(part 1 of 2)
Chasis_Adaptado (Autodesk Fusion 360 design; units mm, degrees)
part number: 2026-02-16-18-52-57-349
description: 18650
part number: Porta baterias 2x18650
description: Porta baterias 2x18650
description: Contacto_Helice_v2.0
part number: Contacto_Helice_v2.0
description: Contacto_plano_v1.0
part number: Contacto_plano_v1.0
description: Bateria 18650
part number: Bateria 18650
description: remache_v1.0
part number: remache_v1.0
description: STEP AP214
part number: DRV8833
part number: esp32_Wroom_30pins_C-Type
description: Part Number
part number: N20 Mini Micro Metall Gear Motor DC 3-6-12V v1
external_derived "DerivadoExterno1"
derived_instance "DerivedInstance1"
derived_instance "DerivedInstance1"
derived_instance "DerivedInstance2"
derived_instance "DerivedInstance3"
derived_instance "DerivedInstance4"
derived_instance "DerivedInstance5"
external_derived "DerivadoExterno2"
derived_instance "DerivedInstance2"
external_derived "DerivadoExterno3"
derived_instance "DerivedInstance3"
external_derived "DerivadoExterno5"
derived_instance "DerivedInstance5"
sketch "Boceto1" plane through (0, 0, 0) normal (0, 0, 1) x axis (1, 0, 0)
position "Posición1"
sketch "Boceto2" plane through (0, 0, 0) normal (0, 0, 1) x axis (1, 0, 0)
sketch "Boceto3" plane through (0, 0, 0) normal (0, 0, 1) x axis (1, 0, 0)
  line L1 (66.5, -10) -> (0, -10)
  line L2 (66.5, -26.4) -> (66.5, -10)
  line L3 (0, -26.4) -> (66.5, -26.4)
  line L4 (0, -10) -> (0, -26.4)
  point P2 (0, -10)
  point P3 (66.5, -10)
  point P5 (0, -26.4)
  horizontal L1
  vertical L2
  horizontal L3
  vertical L4
  dimension "d3" distance P2 P3 = 66.5
  dimension "d4" distance P2 P5 = 16.4
extrude "Extruir1" new body sketch "Boceto3" along normal blind 3.5
move "Desplazar1"
move "Desplazar2" PositionX -33.25 PositionY 128.46 PositionZ 40.82
sketch "Boceto4" plane through (0, 0, 0) normal (0, 0, 1) x axis (1, 0, 0)
  circle C1 centre (20, -70) radius 19
  dimension "d10" diameter C1 = 38
copy_paste_bodies "CopiarPegarCuerpos1"
move "Desplazar4"
sketch "Boceto5" plane through (0, 0, 0) normal (0, 0, 1) x axis (1, 0, 0)
extrude "Extruir3" add of existing geometry blind 15
offset_faces "CarasDesfase3" distance -4
move "Desplazar5"
copy_paste_bodies "CopiarPegarCuerpos2"
move "Desplazar6"
move "Desplazar7"
move "Desplazar8" PositionX -60 PositionY 14.925 PositionZ 0
move "Desplazar9" PositionX -60 PositionY 15 PositionZ 0
move "Desplazar10" PositionX 60 PositionY 15 PositionZ 0
move_face "MoveFace1"
move "Desplazar11"
move "Desplazar12"
move "Desplazar1"
scale "Escala1" ScaleFactor 1.0557
copy_paste "CopiarPegar"
position "Posición2"
hole "Agujero1" HoleDepth 14 HoleDiameter 3 TipAngle 180
position "Posición3"
extrude "Extruir4" add of existing geometry blind 0.5
position "Posición4"
sketch "Boceto6" plane through (0, 0, 0) normal (1, 0, 0) x axis (0, 1, 0)
  line L1 (145.5, 9.7) -> (5.5, 9.7)
  line L2 (145.5, 5.7) -> (145.5, 9.7)
  line L3 (5.5, 5.7) -> (145.5, 5.7)
  line L4 (5.5, 9.7) -> (5.5, 5.7)
  point P2 (5.5, 9.7)
  point P3 (145.5, 9.7)
  point P5 (5.5, 5.7)
  horizontal L1
  vertical L2
  horizontal L3
  vertical L4
  dimension "d33" distance P2 P3 = 140
  dimension "d34" distance P2 P5 = 4
extrude "Extruir5" new body sketch "Boceto6" along normal blind 4
move "Desplazar13"
extrude "Extruir6" add of existing geometry blind 22
extrude "Extruir7" add of existing geometry blind 26
move "Desplazar14"
position "Posición5"
sketch "Boceto7" plane through (0, 0, 0) normal (0, 0, 1) x axis (1, 0, 0)
  line L1 (32, -10) -> (10, -10)
  line L2 (32, -32) -> (32, -10)
  line L3 (10, -32) -> (32, -32)
  line L4 (10, -10) -> (10, -32)
  point P2 (10, -10)
  point P3 (32, -10)
  point P5 (10, -32)
  horizontal L1
  vertical L2
  horizontal L3
  vertical L4
  dimension "d41" distance P2 P3 = 22
  dimension "d42" distance P2 P5 = 22
extrude "Extruir8" new body sketch "Boceto7" along normal blind 15
move "Desplazar15"
move "Desplazar16" PositionX -1 PositionY -32 PositionZ -11
move "Desplazar17" PositionX -11 PositionY 110 PositionZ 0
extrude "Extruir9" add of existing geometry blind 5
sketch "Boceto8" plane through (0, 0, 0) normal (0, 0, 1) x axis (1, 0, 0)
  line L1 (-4, -5) -> (-20, -5)
  line L2 (-4, -35) -> (-4, -5)
  line L3 (-20, -35) -> (-4, -35)
  line L4 (-20, -5) -> (-20, -35)
  point P2 (-20, -5)
  point P3 (-4, -5)
  point P5 (-20, -35)
  horizontal L1
  vertical L2
  horizontal L3
  vertical L4
  dimension "d53" distance P2 P3 = 16
  dimension "d54" distance P2 P5 = 30
extrude "Extruir10" new body sketch "Boceto8" along normal blind 50
offset_faces "CarasDesfase4" distance -10
move "Desplazar18"
offset_faces "CarasDesfase5" distance -0.5
offset_faces "CarasDesfase6" distance -0.5
sketch "Boceto9" plane through (-20, 0, 0) normal (-1, 0, 0) x axis (0, -1, 0)
  line L1 (-8.5715, 10) -> (-21.4287, 10)
  line L2 (-8.5715, 20.3288) -> (-8.5715, 10)
  line L3 (-21.4287, 20.3288) -> (-8.5715, 20.3288)
  line L4 (-21.4287, 10) -> (-21.4287, 20.3288)
  horizontal L1
  vertical L2
  horizontal L3
  vertical L4
extrude "Extruir11" cut of existing geometry blind -26
sketch "Boceto10" plane through (-20, 0, 0) normal (-1, 0, 0) x axis (0, -1, 0)
  line L1 (-0.5646, 13) -> (-5, 13)
  line L2 (-0.5646, 24.0432) -> (-0.5646, 13)
  line L3 (-5, 24.0432) -> (-0.5646, 24.0432)
  line L4 (-5, 13) -> (-5, 24.0432)
  line L5 (-29.5011, 13) -> (-25, 13)
  line L6 (-29.5011, 24.0432) -> (-29.5011, 13)
  line L7 (-25, 24.0432) -> (-29.5011, 24.0432)
  line L8 (-25, 13) -> (-25, 24.0432)
  horizontal L1
  vertical L2
  horizontal L3
  vertical L4
  horizontal L5
  vertical L6
  horizontal L7
  vertical L8
extrude "Extruir12" cut sketch "Boceto10" against normal blind 16
extrude "Extruir13" cut of existing geometry blind -11
copy_paste_bodies "CopiarPegarCuerpos3"
move "Desplazar19"
extrude "Extruir14" cut sketch "Boceto9" against normal blind 43
extrude "Extruir15" cut of existing geometry blind -0.3
extrude "Extruir16" cut of existing geometry blind -0.3
extrude "Extruir17" cut of existing geometry blind -0.1
extrude "Extruir18" add of existing geometry blind 0.3
extrude "Extruir19" add of existing geometry blind 0.1
extrude "Extruir20" cut of existing geometry blind -14
position "Posición6"
sketch "Boceto11" plane through (0, 0, 9.6) normal (0, 0, 1) x axis (-1, 0, 0)
  line L1 (11, -132) -> (11, -110)
  line L2 (-11, -132) -> (11, -132)
  line L3 (-11, -110) -> (-11, -132)
  line L4 (11, -110) -> (-11, -110)
  line L5 (-26, -145.5) -> (-26, -0.5)
  line L6 (26, -145.5) -> (-26, -145.5)
  line L7 (26, -0.5) -> (26, -145.5)
  line L8 (-26, -0.5) -> (26, -0.5)
  line L9 (21.0863, -31.1844) -> (-20.8721, -31.1844)
  line L10 (21.0863, -108.1675) -> (21.0863, -31.1844)
  line L11 (-20.8721, -108.1675) -> (21.0863, -108.1675)
  line L12 (-20.8721, -31.1844) -> (-20.8721, -108.1675)
  line L13 (-22, -109.5) -> (22, -109.5)
  line L14 (-22, -30) -> (-22, -109.5)
  line L15 (22, -30) -> (-22, -30)
  line L16 (22, -109.5) -> (22, -30)
  horizontal L9
  vertical L10
  horizontal L11
  vertical L12
  horizontal L13
  vertical L14
  horizontal L15
  vertical L16
extrude "Extruir21" add sketch "Boceto11" profile of L9 L10 L11 L12 L13 L14 L15 L16 along normal blind 20
extrude "Extruir22" add of existing geometry blind 0.1
sketch "Boceto12" plane through (0, 0, 9.6) normal (0, 0, 1) x axis (-1, 0, 0)
  line L1 (22.1, -30) -> (-22, -30)
  line L2 (22.1, -109.5) -> (22.1, -30)
  line L3 (-22, -109.5) -> (22.1, -109.5)
  line L4 (-22, -30) -> (-22, -109.5)
  line L5 (11, -132) -> (11, -110)
  line L6 (-11, -132) -> (11, -132)
  line L7 (-11, -110) -> (-11, -132)
  line L8 (11, -110) -> (-11, -110)
  line L9 (-26, -145.5) -> (-26, -0.5)
  line L10 (26, -145.5) -> (-26, -145.5)
  line L11 (26, -0.5) -> (26, -145.5)
  line L12 (-26, -0.5) -> (26, -0.5)
  line L13 (26, -109.5) -> (-26, -109.5)
  line L14 (26, -145.5) -> (26, -109.5)
  line L15 (-26, -145.5) -> (26, -145.5)
  line L16 (-26, -109.5) -> (-26, -145.5)
  point P12 (26, -145.5)
  point P16 (26, -145.5)
  point P14 (-26, -109.5)
  horizontal L13
  vertical L14
  horizontal L15
  vertical L16
  coincident P12 P16
  coincident L9 P14
extrude "Extruir23" add sketch "Boceto12" profile of L3 L5 L6 L7 L8 L9 L10 L11 L13 L14 L15 L16 along normal blind 5.4
move "Desplazar20"
position "Posición7"
extrude "Extruir24" add of existing geometry blind 6
extrude "Extruir25" cut of existing geometry blind -6
position "Posición8"
extrude "Extruir26" add of existing geometry blind 2
offset_faces "CarasDesfase7" distance -3
position "Posición9"
extrude "Extruir27" add of existing geometry blind 1
extrude "Extruir28" add of existing geometry blind 1
extrude "Extruir29" add of existing geometry blind 1
extrude "Extruir30" cut of existing geometry blind -0.5
extrude "Extruir31" cut of existing geometry blind -0.5
extrude "Extruir32" cut of existing geometry blind -0.6
split "Dividir1"
move "Desplazar21"
delete_face "SuprimirCaras1"
split "Dividir2"
extrude "Extruir33" cut of existing geometry blind -5
offset_faces "CarasDesfase8" distance -15
move "Desplazar22"
extrude "Extruir34" cut of existing geometry blind -5
extrude "Extruir35" cut of existing geometry blind -3
move "Desplazar23"
move "Desplazar24" PositionX -33.25 PositionY 143.86 PositionZ 0
move "Desplazar25" PositionX -33.25 PositionY 143.86 PositionZ 3
move "Desplazar26"
extrude "Extruir36" add of existing geometry blind 0.6
copy_paste_bodies "CopiarPegarCuerpos4"
move "Desplazar27"
combine "Combinar1"
extrude "Extruir37" add of existing geometry blind 2
sketch "Boceto13" plane through (0, 0, 10.3) normal (0, 0, 1) x axis (-1, 0, 0)
  line L1 (26, -127.5) -> (33.25, -127.5)
  line L2 (11, -127.5) -> (26, -127.5)
  line L3 (-11, -127.5) -> (11, -127.5)
  line L4 (-26, -127.5) -> (-11, -127.5)
  line L5 (-33.25, -127.5) -> (-26, -127.5)
  line L6 (-33.25, -145.86) -> (-33.25, -127.5)
  line L7 (33.25, -145.86) -> (-33.25, -145.86)
  line L8 (33.25, -127.5) -> (33.25, -145.86)
  circle C1 centre (17.9, -131.55) radius 1.85
  circle C2 centre (-17.9, -131.5514) radius 1.85
  dimension "d146" diameter C1 = 3.7
  dimension "d147" diameter C2 = 3.7
extrude "Extruir38" cut sketch "Boceto13" profile of C1 C2 against normal blind 15
offset_faces "CarasDesfase9" distance 2
sketch "Boceto14" plane through (0, 0, 17) normal (0, 0, 1) x axis (-1, 0, 0)
  line L1 (26, -127.5) -> (-26, -127.5)
  line L2 (26, -109.5) -> (26, -127.5)
  line L3 (23.1, -109.5) -> (26, -109.5)
  line L4 (23.1, -110.5) -> (23.1, -109.5)
  line L5 (-23, -110.5) -> (23.1, -110.5)
  line L6 (-23, -109.5) -> (-23, -110.5)
  line L7 (-26, -109.5) -> (-23, -109.5)
  line L8 (-26, -127.5) -> (-26, -109.5)
  circle C1 centre (-7, -119) radius 1
  circle C2 centre (8, -119) radius 1
extrude "Extruir39" cut of existing geometry blind -3
extrude "Extruir40" add sketch "Boceto14" along normal blind 1
extrude "Extruir41" add of existing geometry blind 1.5
sketch "Boceto15" plane through (0, 0, 41.1032) normal (0, 0, 1) x axis (-1, 0, 0)
copy_paste_bodies "CopiarPegarCuerpos6"
move "Desplazar30"
move "Desplazar31"
hole "Agujero10" HoleDepth 40 HoleDiameter 3.3 TipAngle 180
sketch "Boceto16" plane through (0, 0, 0) normal (0, 0, 1) x axis (1, 0, 0)
  line L1 (-27, -69) -> (-30, -69)
  line L2 (-27, -71) -> (-27, -69)
  line L3 (-30, -71) -> (-27, -71)
  line L4 (-30, -69) -> (-30, -71)
  horizontal L1
  vertical L2
  horizontal L3
  vertical L4
extrude "Extruir42" new body sketch "Boceto16" along normal blind 30
move "Desplazar32"
offset_faces "CarasDesfase10" distance -5
move "Desplazar33"
move "Desplazar34"
move "Desplazar35"
move "Desplazar36"
move "Desplazar37"
move "Desplazar38"
move "Desplazar39"
sketch "Boceto17" plane through (0, 0, 0) normal (0, 0, 1) x axis (1, 0, 0)
  line L1 (-50, -50) -> (-90, -50)
  line L2 (-50, -90) -> (-50, -50)
  line L3 (-90, -90) -> (-50, -90)
  line L4 (-90, -50) -> (-90, -90)
  horizontal L1
  vertical L2
  horizontal L3
  vertical L4
combine "Combinar3"
move "Desplazar40"
extrude "Extruir43" new body sketch "Boceto17" along normal blind 2
copy_paste_bodies "CopiarPegarCuerpos7"
move "Desplazar41"
move "Desplazar42"
offset_faces "CarasDesfase11" distance -1.5
offset_faces "CarasDesfase12" distance -1.5
move "Desplazar43"
sketch "Boceto18" plane through (0, 0, 2) normal (0, 0, 1) x axis (-1, 0, 0)
  line L1 (50, 90) -> (90, 90)
  line L2 (50, 50) -> (50, 90)
  line L3 (90, 50) -> (50, 50)
  line L4 (90, 90) -> (90, 50)
  circle C1 centre (70, 70) radius 15.25
  dimension "d168" diameter C1 = 30.5
extrude "Extruir44" add sketch "Boceto18" along normal blind 30
hole "Agujero11" HoleDepth 40 HoleDiameter 3.3 TipAngle 180
sketch "Boceto19" plane through (0, 0, 68.4803) normal (0, 0, 1) x axis (-1, 0, 0)
  line L1 (25.8803, 69.0639) -> (25.8803, 68.9085)
  line L2 (23.8803, 69.0639) -> (25.8803, 69.0639)
  line L3 (23.8803, 68.8793) -> (23.8803, 69.0639)
  circle C1 centre (24.8611, 70.2061) radius 12
  arc A1 centre (24.8611, 70.2061) radius 1.65 clockwise from (23.8803, 68.8793) to (25.8803, 68.9085)
  circle C2 centre (24.8611, 70.2061) radius 7.5
  concentric C1 C2
  dimension "d174" diameter C2 = 15
extrude "Extruir45" cut sketch "Boceto19" profile of A1 L1 L2 L3 C2 against normal blind 10
move "Desplazar44"
move "Desplazar45"
extrude "Extruir46" add of existing geometry blind 5
extrude "Extruir47" cut of existing geometry blind -1
move "Desplazar46"
extrude "Extruir48" add of existing geometry blind 1
extrude "Extruir49" add of existing geometry blind 1
sketch "Boceto20" plane through (-24.1, 0, 0) normal (-1, 0, 0) x axis (0, -1, 0)
sketch "Boceto21" plane through (0, 0, 0) normal (0, 0, 1) x axis (1, 0, 0)
  line L1 (141.1, 38) -> (93, 38)
  line L2 (141.1, 118.5) -> (141.1, 38)
  line L3 (93, 118.5) -> (141.1, 118.5)
  line L4 (93, 38) -> (93, 118.5)
  circle C1 centre (57, 56) radius 2.5
  point P3 (93, 38)
  point P4 (141.1, 38)
  point P6 (93, 118.5)
  horizontal L1
  vertical L2
  horizontal L3
  vertical L4
  dimension "d185" diameter C1 = 5
  dimension "d186" distance P3 P4 = 48.1
  dimension "d187" distance P3 P6 = 80.5
extrude "Extruir50" new body sketch "Boceto21" profile of L1 L2 L3 L4 along normal blind 2.5
sketch "Boceto22" plane through (0, 0, 0) normal (1, 0, 0) x axis (0, 1, 0)
sketch "Boceto23" plane through (0, 0, 0) normal (0, 0, 1) x axis (1, 0, 0)
  circle C1 centre (66, 34) radius 2.5
  dimension "d190" diameter C1 = 5
move "Desplazar47"
extrude "Extruir51" new body sketch "Boceto23" along normal blind 6
move "Desplazar48"
copy_paste_bodies "CopiarPegarCuerpos8"
move "Desplazar49"
copy_paste_bodies "CopiarPegarCuerpos9"
move "Desplazar50"
combine "Combinar4"
move "Desplazar51"
combine "Combinar5"
extrude "Extruir52" cut of existing geometry blind -3.4
extrude "Extruir53" cut of existing geometry blind -15
extrude "Extruir54" cut of existing geometry blind -2.6
extrude "Extruir55" cut of existing geometry blind -0.8
extrude "Extruir56" cut of existing geometry blind -0.1
move "Desplazar52"
hole "Agujero12" HoleDepth 10 HoleDiameter 3.3 TipAngle 180
hole "Agujero13" HoleDepth 10 HoleDiameter 3.3 TipAngle 180
extrude "Extruir57" cut of existing geometry blind -1.5
sketch "Boceto24" plane through (0, 0, 22.2) normal (0, 0, 1) x axis (-1, 0, 0)
  line L1 (24.1, -108.7912) -> (24.1, -110.5)
  line L2 (24.1, -110.5) -> (22.4379, -110.5)
  arc A1 centre (24.0869, -110.4412) radius 1.65 clockwise from (22.4379, -110.5) to (24.1, -108.7912)
  circle C1 centre (24.0869, -110.4412) radius 2.4953
  concentric A1 C1
extrude "Extruir58" cut sketch "Boceto24" along normal blind 4.8
sketch "Boceto25" plane through (0, 0, 22.2) normal (0, 0, 1) x axis (-1, 0, 0)
  line L1 (-24, -31.6382) -> (-24, -30)
  line L2 (-24, -30) -> (-22.364, -30)
  arc A1 centre (-24.014, -29.9882) radius 1.65 clockwise from (-22.364, -30) to (-24, -31.6382)
  circle C1 centre (-24.014, -29.9882) radius 2.5
  concentric A1 C1
  dimension "d213" diameter C1 = 5
extrude "Extruir59" cut sketch "Boceto25" along normal blind 4.8
hole "Agujero14" HoleDepth 50 HoleDiameter 4 TipAngle 180
hole "Agujero15" HoleDepth 50 HoleDiameter 4 TipAngle 180
hole "Agujero16" HoleDepth 7 HoleDiameter 4 TipAngle 180
hole "Agujero17" HoleDepth 7 HoleDiameter 4 TipAngle 180
extrude "Extruir60" cut of existing geometry blind -1
hole "Agujero18" HoleDepth 40 HoleDiameter 3.4 TipAngle 180
extrude "Extruir61" add of existing geometry blind 1.5
move "Desplazar53"
extrude "Extruir62" cut of existing geometry blind -0.5
extrude "Extruir63" cut of existing geometry blind -0.03
offset_faces "CarasDesfase13" distance 0.3
offset_faces "CarasDesfase14" distance 0.2
move "Desplazar54"
split "Dividir3"
hole "Agujero20" HoleDepth 45 HoleDiameter 3.4 TipAngle 180
hole "Agujero21" HoleDepth 45 HoleDiameter 3.4 TipAngle 180
hole "Agujero22" HoleDepth 45 HoleDiameter 3.4 TipAngle 180
hole "Agujero23" HoleDepth 45 HoleDiameter 3.4 TipAngle 180
move "Desplazar55"
sketch "Boceto30" plane through (0, 0, 0) normal (1, 0, 0) x axis (0, 1, 0)
  line L1 (-32, 30) -> (-30, 30)
  line L2 (-32, 7) -> (-32, 30)
  line L3 (-30, 7) -> (-32, 7)
  line L4 (-30, 30) -> (-30, 7)
  horizontal L1
  vertical L2
  horizontal L3
  vertical L4
extrude "Extruir65" cut sketch "Boceto30" against normal blind 1.1
circular_pattern "Patrón C" countU 18 TotalAngle 360
revolve "Revolución1" AlongAngle 360
revolve "Revolución2" AlongAngle 360
position "Posición10"
extrude "Extruir66" add of existing geometry blind 2
position "Posición11"
split "Dividir4"
move "Desplazar56"
extrude "Extruir67" add of existing geometry blind 10
extrude "Extruir68" add of existing geometry blind 3
move "Desplazar57"
extrude "Extruir69" add of existing geometry blind 2
offset_faces "CarasDesfase15" distance -1
extrude "Extruir70" add of existing geometry blind 1.5
extrude "Extruir71" add of existing geometry blind 0.5
hole "Agujero28" HoleDepth 100 HoleDiameter 3.5 TipAngle 180
hole "Agujero29" HoleDepth 100 HoleDiameter 3.5 TipAngle 180
hole "Agujero30" HoleDepth 100 HoleDiameter 3.5 TipAngle 180
hole "Agujero31" HoleDepth 100 HoleDiameter 3.5 TipAngle 180
hole "Agujero32" HoleDepth 100 HoleDiameter 3.5 TipAngle 180
hole "Agujero33" HoleDepth 100 HoleDiameter 3.5 TipAngle 180
hole "Agujero34" HoleDepth 100 HoleDiameter 3.5 TipAngle 180
hole "Agujero35" HoleDepth 100 HoleDiameter 3.5 TipAngle 180
combine "Combinar6"
offset_faces "CarasDesfase16" distance 0.5
offset_faces "CarasDesfase17" distance 0.5
move "Desplazar58"
offset_faces "CarasDesfase18" distance -3
move "Desplazar59"
move "Desplazar60"
move "Desplazar61"
sketch "Boceto31" plane through (0, 0, 6.8) normal (0, 0, -1) x axis (1, 0, 0)
  line L1 (11, -127.5) -> (26, -127.5)
  line L2 (-11, -127.5) -> (11, -127.5)
  line L3 (-26, -127.5) -> (-11, -127.5)
  line L4 (-26, -120.25) -> (-26, -127.5)
  line L5 (-33.25, -145.86) -> (-33.25, -127.5)
  line L6 (33.25, -145.86) -> (-33.25, -145.86)
  line L7 (33.25, -127.5) -> (33.25, -145.86)
  line L8 (26, -127.5) -> (26, -120.25)
  line L9 (34, -128) -> (-34, -128)
  line L10 (34, -146) -> (34, -128)
  line L11 (-34, -146) -> (34, -146)
  line L12 (-34, -128) -> (-34, -146)
  arc A1 centre (-26, -127.5) radius 7.25 clockwise from (-33.25, -127.5) to (-26, -120.25)
  arc A2 centre (26, -127.5) radius 7.25 clockwise from (26, -120.25) to (33.25, -127.5)
  arc A3 centre (17.9, -131.5514) radius 1.85 clockwise from (19.683, -131.0577) to (19.3644, -130.4208)
  arc A4 centre (26, -127.5) radius 7.25 clockwise from (19.683, -131.0577) to (19.3644, -130.4208)
  arc A5 centre (-17.9, -131.55) radius 1.85 clockwise from (-19.363, -130.4177) to (-19.6836, -131.0589)
  arc A6 centre (-26, -127.5) radius 7.25 clockwise from (-19.363, -130.4177) to (-19.6836, -131.0589)
  horizontal L9
  vertical L10
  horizontal L11
  vertical L12
extrude "Extruir72" new body sketch "Boceto31" profile of L9 L10 L11 L12 along normal blind 3
shell "Vaciado" innerThickness 0.5
extrude "Extruir73" add of existing geometry blind 6
extrude "Extruir74" cut of existing geometry blind -3.5
extrude "Extruir75" add of existing geometry blind 0.9
sketch "Boceto32" plane through (0, 0, 3) normal (0, 0, -1) x axis (1, 0, 0)
sketch "Boceto33" plane through (0, 128, 0) normal (0, -1, 0) x axis (1, 0, 0)
  line L1 (34, 0.3) -> (-34, 0.3)
  line L2 (34, 6.7) -> (34, 0.3)
  line L3 (-34, 6.7) -> (34, 6.7)
  line L4 (-34, 0.3) -> (-34, 6.7)
  line L5 (-14.9733, 0.3) -> (-21.0163, 0.3)
  line L6 (-14.9733, 6.7) -> (-14.9733, 0.3)
  line L7 (-21.0163, 6.7) -> (-14.9733, 6.7)
  line L8 (-21.0163, 0.3) -> (-21.0163, 6.7)
  line L9 (20.8752, 0.3) -> (15.0029, 0.3)
  line L10 (20.8752, 6.7) -> (20.8752, 0.3)
  line L11 (15.0029, 6.7) -> (20.8752, 6.7)
  line L12 (15.0029, 0.3) -> (15.0029, 6.7)
  point P8 (-14.9733, 6.7)
  point P6 (-21.0163, 0.3)
  point P12 (20.8752, 6.7)
  point P10 (15.0029, 0.3)
  horizontal L5
  vertical L6
  horizontal L7
  vertical L8
  coincident L3 P8
  coincident L1 P6
  horizontal L9
  vertical L10
  horizontal L11
  vertical L12
  coincident L3 P12
  coincident L1 P10
extrude "Extruir76" cut sketch "Boceto33" profile of L1 L3 L5 L6 L7 L8 L9 L10 L11 L12 against normal blind 6
extrude "Extruir77" add of existing geometry blind 0.25
extrude "Extruir78" add of existing geometry blind 3
extrude "Extruir79" cut of existing geometry blind -3
extrude "Extruir80" cut of existing geometry blind -6
extrude "Extruir81" add of existing geometry blind 0.5
move "Desplazar62"
move "Desplazar63"
extrude "Extruir82" add of existing geometry blind 2
extrude "Extruir84" cut of existing geometry blind -1
extrude "Extruir85" cut of existing geometry blind -0.3
offset_faces "CarasDesfase24" distance 0.5
extrude "Extruir86" cut of existing geometry blind -0.5
copy_paste_bodies "CopiarPegarCuerpos16"
move "Desplazar70"
scale "Escala1" ScaleZ 0.9
offset_faces "CarasDesfase25" distance -1.5
move "Desplazar71"
offset_faces "CarasDesfase26" distance 1
move "Desplazar72"
scale "Escala2" ScaleX 1.1 ScaleY 1.1
move "Desplazar73"
offset_faces "CarasDesfase27" distance -1
offset_faces "CarasDesfase28" distance 1.8
offset_faces "CarasDesfase29" distance -2
offset_faces "CarasDesfase30" distance 0.2
offset_faces "CarasDesfase31" distance -2.5
scale "Escala3" ScaleX 0.9 ScaleY 0.9
move "Desplazar74"
move "Desplazar75"
move "Desplazar76"
move "Desplazar77"
move "Desplazar78"
split "Dividir5"
split "Dividir6"
move "Desplazar79"
move "Desplazar80"
extrude "Extruir89" add of existing geometry blind 3
split "Dividir7"
offset_faces "CarasDesfase32" distance -70
position "Posición12"
sketch "Boceto35" plane through (0, 0, 0) normal (0, 0, 1) x axis (1, 0, 0)
move "Desplazar82"
move "Desplazar83"
sketch "Boceto36" plane through (0, 0, 10.3) normal (0, 0, 1) x axis (-1, 0, 0)
  line L1 (-33.25, -145.86) -> (-33.25, -127.5)
  line L2 (33.25, -145.86) -> (-33.25, -145.86)
  line L3 (33.25, -127.5) -> (33.25, -145.86)
  line L4 (26, -127.5) -> (26, -120.25)
  line L5 (11, -127.5) -> (26, -127.5)
  line L6 (-11, -127.5) -> (11, -127.5)
  line L7 (-26, -127.5) -> (-11, -127.5)
  line L8 (-26, -120.25) -> (-26, -127.5)
  line L9 (11, -127.5) -> (-11, -127.5)
  line L10 (11, -132.5) -> (11, -127.5)
  line L11 (-11, -132.5) -> (11, -132.5)
  line L12 (-11, -127.5) -> (-11, -132.5)
  arc A1 centre (26, -127.5) radius 7.25 clockwise from (26, -120.25) to (33.25, -127.5)
  arc A2 centre (-26, -127.5) radius 7.25 clockwise from (-33.25, -127.5) to (-26, -120.25)
  arc A3 centre (-17.9, -131.5514) radius 1.85 clockwise from (-19.3644, -130.4208) to (-19.683, -131.0577)
  arc A4 centre (-26, -127.5) radius 7.25 clockwise from (-19.3644, -130.4208) to (-19.683, -131.0577)
  arc A5 centre (17.9, -131.55) radius 1.85 clockwise from (19.6836, -131.0589) to (19.363, -130.4177)
  arc A6 centre (26, -127.5) radius 7.25 clockwise from (19.6836, -131.0589) to (19.363, -130.4177)
  point P9 (-11, -127.5)
  point P18 (-11, -127.5)
  point P19 (11, -127.5)
  point P21 (-11, -132.5)
  horizontal L9
  vertical L10
  horizontal L11
  vertical L12
  coincident P9 P18
  dimension "d380" distance P18 P19 = 22
  dimension "d381" distance P18 P21 = 5
extrude "Extruir90" cut sketch "Boceto36" profile of L6 L9 L10 L11 L12 against normal blind 15
combine "Combinar7"
extrude "Extruir91" cut of existing geometry blind -3
extrude "Extruir92" cut of existing geometry blind -3
move "Desplazar84"
move "Desplazar85"
move "Desplazar86"
move "Desplazar87"
move "Desplazar88"
move "Desplazar89"
combine "Combinar8"
extrude "Extruir93" cut of existing geometry blind 1
extrude "Extruir94" add of existing geometry blind 1
extrude "Extruir95" add of existing geometry blind 1
move "Desplazar90"
move "Desplazar91"
move "Desplazar92"
move "Desplazar93"
move "Desplazar94"
extrude "Extruir96" cut of existing geometry blind -13
extrude "Extruir97" cut of existing geometry blind -7
move "Desplazar95"
move "Desplazar96"
sketch "Boceto37" plane through (0, 0, 9.6) normal (0, 0, 1) x axis (-1, 0, 0)
  line L1 (26, -31.1844) -> (-26, -31.1844)
  line L2 (26, 5.5) -> (26, -31.1844)
  line L3 (-26, 5.5) -> (26, 5.5)
  line L4 (-26, -31.1844) -> (-26, 5.5)
  line L5 (26, -18.4) -> (4.1, -18.4)
  line L6 (26, -31.1844) -> (26, -18.4)
  line L7 (4.1, -31.1844) -> (26, -31.1844)
  line L8 (4.1, -18.4) -> (4.1, -31.1844)
  line L9 (-26, -18.4) -> (4.1, -18.4)
  line L10 (-26, -31) -> (-26, -18.4)
  line L11 (4.1, -31) -> (-26, -31)
  line L12 (4.1, -18.4) -> (4.1, -31)
  line L13 (-1, -7) -> (1, -7)
  line L14 (-1, -18.4) -> (-1, -7)
  line L15 (1, -18.4) -> (-1, -18.4)
  line L16 (1, -7) -> (1, -18.4)
  line L17 (-26, 5.5) -> (26, 5.5)
  line L18 (-26, -5.5) -> (-26, 5.5)
  line L19 (26, -5.5) -> (-26, -5.5)
  line L20 (26, 5.5) -> (26, -5.5)
  line L21 (-1, -7) -> (1, -7)
  line L22 (-1, -5.5) -> (-1, -7)
  line L23 (1, -5.5) -> (-1, -5.5)
  line L24 (1, -7) -> (1, -5.5)
  circle C1 centre (16.9761, -25.1758) radius 1.75
  circle C2 centre (7.0114, -25.1758) radius 1.75
  circle C3 centre (16.9759, 1.2458) radius 1.75
  circle C4 centre (7.0048, 1.2479) radius 1.75
  circle C5 centre (-7.0062, -25.2517) radius 1.75
  circle C6 centre (-16.9814, -25.2578) radius 1.75
  circle C7 centre (-7.0116, 1.2465) radius 1.75
  circle C8 centre (-16.994, 1.2507) radius 1.75
  point P11 (26, -31.1844)
  point P16 (26, -31.1844)
  point P19 (-26, -31)
  point P23 (-1, -18.4)
  point P27 (-26, -5.5)
  point P12 (26, 5.5)
  point P25 (26, 5.5)
  point P21 (1, -7)
  point P22 (-1, -7)
  point P29 (-1, -7)
  horizontal L5
  vertical L6
  horizontal L7
  vertical L8
  coincident P11 P16
  horizontal L9
  vertical L10
  horizontal L11
  vertical L12
  coincident L4 P19
  horizontal L13
  vertical L14
  horizontal L15
  vertical L16
  coincident L9 P23
  horizontal L17
  vertical L18
  horizontal L19
  vertical L20
  coincident L4 P27
  coincident P12 P25
  horizontal L21
  vertical L22
  horizontal L23
  vertical L24
  dimension "d398" distance P21 P22 = 2
  dimension "d399" distance P21 P29 = 2
extrude "Extruir98" add sketch "Boceto37" along normal blind 9
move "Desplazar97"
extrude "Extruir99" add of existing geometry blind 1.7
extrude "Extruir100" cut of existing geometry blind -21.9
extrude "Extruir101" add of existing geometry blind 10.7
combine "Combinar9"
extrude "Extruir102" add of existing geometry blind 10
move "Desplazar98"
move_face "MoveFace2"
hole "Agujero37" HoleDepth 18 HoleDiameter 5 TipAngle 180
hole "Agujero38" HoleDepth 18 HoleDiameter 5 TipAngle 180
hole "Agujero39" HoleDepth 18 HoleDiameter 7 TipAngle 180
hole "Agujero40" HoleDepth 18 HoleDiameter 7 TipAngle 180
extrude "Extruir103" add of existing geometry blind 8
sketch "Boceto38" plane through (11, 0, 0) normal (-1, 0, 0) x axis (0, -1, 0)
  line L1 (-41, 15.5) -> (-41, 3)
  line L2 (-57.5, 15.5) -> (-41, 15.5)
  line L3 (-57.5, 10.3) -> (-57.5, 15.5)
  line L4 (-62.5, 10.3) -> (-57.5, 10.3)
  line L5 (-62.5, 6.8) -> (-62.5, 10.3)
  line L6 (-57.5, 6.8) -> (-62.5, 6.8)
  line L7 (-57.5, 3) -> (-57.5, 6.8)
  line L8 (-41, 3) -> (-57.5, 3)
  line L9 (-62.5, 6.8) -> (-57.5, 6.8)
  line L10 (-62.5, 10.3) -> (-62.5, 6.8)
  line L11 (-57.5, 10.3) -> (-62.5, 10.3)
  line L12 (-57.5, 6.8) -> (-57.5, 10.3)
  point P6 (-62.5, 10.3)
  point P12 (-62.5, 10.3)
  point P8 (-57.5, 6.8)
  point P10 (-57.5, 6.8)
  horizontal L9
  vertical L10
  horizontal L11
  vertical L12
  coincident P6 P12
  coincident P8 P10
extrude "Extruir104" cut sketch "Boceto38" profile of L4 L5 L6 L9 L10 L11 L12 along normal blind 26
extrude "Extruir105" cut of existing geometry blind 30
extrude "Extruir106" cut of existing geometry blind -0.4
extrude "Extruir107" cut of existing geometry blind -0.4
sketch "Boceto39" plane through (0, 0, 16.5) normal (0, 0, 1) x axis (-1, 0, 0)
  line L1 (-26, -57.5) -> (-26, -31.1844)
  line L2 (26, -57.5) -> (-26, -57.5)
  line L3 (26, -31.1844) -> (26, -57.5)
  line L4 (-26, -31.1844) -> (26, -31.1844)
  line L5 (38.65, -33.5) -> (-39, -33.5)
  line L6 (38.65, -76.5) -> (38.65, -33.5)
  line L7 (-39, -76.5) -> (38.65, -76.5)
  line L8 (-39, -33.5) -> (-39, -76.5)
  circle C1 centre (17.9269, -53.5553) radius 2.5
  circle C2 centre (-17.941, -53.2363) radius 2.5
  circle C3 centre (-7, -49) radius 1
  circle C4 centre (8, -49) radius 1
  horizontal L5
  vertical L6
  horizontal L7
  vertical L8
extrude "Extruir108" add sketch "Boceto39" profile of L1 L2 L3 L5 L6 L7 L8 against normal blind 3
extrude "Extruir109" add of existing geometry blind 3
hole "Agujero41" HoleDepth 18 HoleDiameter 3 TipAngle 180
hole "Agujero42" HoleDepth 18 HoleDiameter 3 TipAngle 180
work_plane "PlanoDeObra" AlongDistance 0 ExtraOffset 0
extrude "Extruir110" add of existing geometry blind 5
split "Dividir8"
extrude "Extruir111" add of existing geometry blind 13
extrude "Extruir112" add of existing geometry blind 13
split "Dividir9"
combine "Combinar10"
sketch "Boceto40" plane through (0, 0, 20.3) normal (0, 0, 1) x axis (-1, 0, 0)
  line L1 (26, -31.0113) -> (-26, -31.0113)
  line L2 (26, -18.4) -> (26, -31.0113)
  line L3 (1, -18.4) -> (26, -18.4)
  line L4 (1, -5.5) -> (1, -18.4)
  line L5 (26, -5.5) -> (1, -5.5)
  line L6 (26, 5.5) -> (26, -5.5)
  line L7 (-26, 5.5) -> (26, 5.5)
  line L8 (-26, -5.5) -> (-26, 5.5)
  line L9 (-1, -5.5) -> (-26, -5.5)
  line L10 (-1, -18.4) -> (-1, -5.5)
  line L11 (-26, -18.4) -> (-1, -18.4)
  line L12 (-26, -31.0113) -> (-26, -18.4)
  line L13 (5.5, -18.4) -> (1, -18.4)
  line L14 (5.5, -5.5) -> (5.5, -18.4)
  line L15 (1, -5.5) -> (5.5, -5.5)
  line L16 (1, -18.4) -> (1, -5.5)
  line L17 (-5.5, -18.4) -> (-1, -18.4)
  line L18 (-5.5, -5.5) -> (-5.5, -18.4)
  line L19 (-1, -5.5) -> (-5.5, -5.5)
  line L20 (-1, -18.4) -> (-1, -5.5)
  circle C1 centre (16.9761, -25.1758) radius 1.75
  circle C2 centre (7.0114, -25.1758) radius 1.75
  circle C3 centre (16.9759, 1.2458) radius 1.75
  circle C4 centre (7.0048, 1.2479) radius 1.75
  circle C5 centre (-7.0062, -25.2517) radius 1.75
  circle C6 centre (-16.9814, -25.2578) radius 1.75
  circle C7 centre (-7.0116, 1.2465) radius 1.75
  circle C8 centre (-16.994, 1.2507) radius 1.75
  point P13 (1, -18.4)
  point P22 (1, -18.4)
  point P20 (-1, -18.4)
  point P26 (-1, -18.4)
  point P23 (5.5, -18.4)
  point P27 (-5.5, -18.4)
  horizontal L13
  vertical L14
  horizontal L15
  vertical L16
  coincident P13 P22
  horizontal L17
  vertical L18
  horizontal L19
  vertical L20
  coincident P20 P26
  dimension "d450" distance P22 P23 = 4.5
  dimension "d451" distance P26 P27 = 4.5
extrude "Extruir113" new body sketch "Boceto40" profile of L3 L4 L5 L9 L10 L11 L13 L14 L15 L16 L17 L18 L19 L20 along normal blind 50
extrude "Extruir114" cut of existing geometry blind -50
combine "Combinar11"
copy_paste_bodies "CopiarPegarCuerpos17"
move "Desplazar99"
copy_paste_bodies "CopiarPegarCuerpos18"
move "Desplazar100"
copy_paste_bodies "CopiarPegarCuerpos19"
move "Desplazar101"
copy_paste_bodies "CopiarPegarCuerpos20"
move "Desplazar102"
extrude "Extruir115" cut of existing geometry blind -0.3
extrude "Extruir116" cut of existing geometry blind -0.2
extrude "Extruir117" cut of existing geometry blind -0.1
extrude "Extruir118" add of existing geometry blind 1
extrude "Extruir119" cut of existing geometry blind -1
extrude "Extruir120" add of existing geometry blind 0.1
copy_paste_bodies "CopiarPegarCuerpos21"
move "Desplazar103"
extrude "Extruir121" add of existing geometry blind 0.1
extrude "Extruir122" cut of existing geometry blind -3.7
extrude "Extruir123" cut of existing geometry blind -6
extrude "Extruir124" add of existing geometry blind 1.6
extrude "Extruir125" cut of existing geometry blind -0.1
extrude "Extruir126" add of existing geometry blind 1
hole "Agujero43" HoleDepth 20 HoleDiameter 3 TipAngle 180 CBDepth 2 CBDiameter 5.5
hole "Agujero44" HoleDepth 20 HoleDiameter 3 TipAngle 180 CBDepth 2 CBDiameter 5.5
hole "Agujero45" HoleDepth 20 HoleDiameter 3 TipAngle 180 CBDepth 2 CBDiameter 5.5
hole "Agujero46" HoleDepth 20 HoleDiameter 3 TipAngle 180 CBDepth 2 CBDiameter 5.5
hole "Agujero47" HoleDepth 20 HoleDiameter 3 TipAngle 180 CBDepth 2 CBDiameter 5.5
hole "Agujero48" HoleDepth 20 HoleDiameter 3 TipAngle 180 CBDepth 2 CBDiameter 5.5
hole "Agujero49" HoleDepth 20 HoleDiameter 3 TipAngle 180 CBDepth 2 CBDiameter 5.5
hole "Agujero50" HoleDepth 20 HoleDiameter 3 TipAngle 180 CBDepth 2 CBDiameter 5.5
split "Dividir10"
move "Desplazar104"
move "Desplazar105"
move "Desplazar106"
move "Desplazar107"
move_face "MoveFace3"
move "Desplazar108"
move "Desplazar109"
delete_face "SuprimirCaras2"
delete_face "SuprimirCaras3"
delete_face "SuprimirCaras4"
delete_face "SuprimirCaras5"
delete_face "SuprimirCaras6"
delete_face "SuprimirCaras7"
hole "Agujero51" HoleDepth 20 HoleDiameter 3.3 TipAngle 180
hole "Agujero52" HoleDepth 20 HoleDiameter 3.3 TipAngle 180
hole "Agujero53" HoleDepth 20 HoleDiameter 3.3 TipAngle 180
hole "Agujero54" HoleDepth 20 HoleDiameter 3.3 TipAngle 180
hole "Agujero55" HoleDepth 20 HoleDiameter 3.3 TipAngle 180
hole "Agujero56" HoleDepth 20 HoleDiameter 3.3 TipAngle 180
hole "Agujero57" HoleDepth 20 HoleDiameter 3.3 TipAngle 180
hole "Agujero58" HoleDepth 20 HoleDiameter 3.3 TipAngle 180
extrude "Extruir127" add of existing geometry blind 2
position "Posición13"
extrude "Extruir128" cut of existing geometry blind -51
extrude "Extruir129" cut of existing geometry blind -71
position "Posición14"
extrude "Extruir130" cut of existing geometry blind -0.1
extrude "Extruir131" cut of existing geometry blind -2
delete_face "SuprimirCaras8"
hole "Agujero59" HoleDepth 40 HoleDiameter 3.2 TipAngle 180
sketch "Boceto41" plane through (0, 0, 22.9998) normal (0, 0, 1) x axis (-1, 0, 0)
  line L1 (64.6288, 32.0122) -> (67.1268, 32.0122)
  line L2 (64.6288, 30.0122) -> (64.6288, 32.0122)
  line L3 (67.1268, 30.0122) -> (64.6288, 30.0122)
  line L4 (67.1268, 32.0122) -> (67.1268, 30.0122)
  line L5 (64.6288, 30.0122) -> (67.1268, 32.0122)
  line L6 (67.1268, 30.0122) -> (64.6288, 32.0122)
  circle C1 centre (65.8778, 31.0122) radius 1.6
  circle C2 centre (65.8778, 31.0122) radius 8.5
  point P7 (65.8778, 31.0122)
  point P3 (67.1268, 32.0122)
  point P2 (65.8778, 31.0122)
  point P4 (64.6288, 32.0122)
  point P5 (64.6288, 30.0122)
  horizontal L1
  perpendicular L1 L2
  parallel L1 L3
  parallel L2 L4
  coincident L5 P7
  coincident L6 P7
  coincident C1 P3
  coincident P2 P7
  dimension "d557" distance P4 P5 = 2
extrude "Extruir132" add sketch "Boceto41" profile of C1 L3 against normal blind 17
move "Desplazar1"
move "Desplazar110"
position "Posición15"
extrude "Extruir133" cut of existing geometry blind -1.05
extrude "Extruir134" cut of existing geometry blind -0.8
extrude "Extruir135" add of existing geometry blind 1
move "Desplazar111"
extrude "Extruir136" cut of existing geometry blind -1
extrude "Extruir137" cut of existing geometry blind -1
move "Desplazar112"
hole "Agujero60" HoleDepth 40 HoleDiameter 3.2 TipAngle 180
hole "Agujero61" HoleDepth 40 HoleDiameter 3.2 TipAngle 180
hole "Agujero62" HoleDepth 40 HoleDiameter 3.2 TipAngle 180
hole "Agujero63" HoleDepth 40 HoleDiameter 3.2 TipAngle 180
hole "Agujero64" HoleDepth 40 HoleDiameter 3.2 TipAngle 180
hole "Agujero65" HoleDepth 40 HoleDiameter 3.2 TipAngle 180
hole "Agujero66" HoleDepth 40 HoleDiameter 3.2 TipAngle 180
hole "Agujero67" HoleDepth 40 HoleDiameter 3.2 TipAngle 180
delete_face "SuprimirCaras9"
delete_face "SuprimirCaras10"
extrude "Extruir138" add of existing geometry blind 2
extrude "Extruir139" cut of existing geometry blind -13
hole "Agujero68" HoleDepth 40 HoleDiameter 3.2 TipAngle 180
hole "Agujero69" HoleDepth 40 HoleDiameter 3.2 TipAngle 180
move "Desplazar113"
move "Desplazar114"
sketch "Boceto42" plane through (0, 0, 18.4363) normal (0, 0, 1) x axis (-1, 0, 0)
  line L1 (-21.5363, 13.7675) -> (21.4222, 13.7675)
  line L2 (-21.5363, -63.8156) -> (-21.5363, 13.7675)
  line L3 (21.4222, -63.8156) -> (-21.5363, -63.8156)
  line L4 (21.4222, 13.7675) -> (21.4222, -63.8156)
  line L5 (-10.9966, -41) -> (11, -41)
  line L6 (-10.9966, -57.5027) -> (-10.9966, -41)
  line L7 (11, -57.5027) -> (-10.9966, -57.5027)
  line L8 (11, -41) -> (11, -57.5027)
  circle C1 centre (-17.9, -61.5514) radius 1.6
  circle C2 centre (-7.0062, -25.2517) radius 1.6
  circle C3 centre (16.9761, -25.1758) radius 1.6
  circle C4 centre (16.9759, 1.2458) radius 1.6
  circle C5 centre (7.0048, 1.2479) radius 1.6
  circle C6 centre (-7.0116, 1.2465) radius 1.6
  circle C7 centre (-16.994, 1.2507) radius 1.6
  circle C8 centre (7.0114, -25.1758) radius 1.6
  circle C9 centre (-16.9814, -25.2578) radius 1.6
  circle C10 centre (17.9, -61.55) radius 1.6
  horizontal L5
  vertical L6
  horizontal L7
  vertical L8
extrude "Extruir140" cut sketch "Boceto42" profile of L5 L6 L7 L8 against normal blind 1.5
extrude "Extruir141" cut of existing geometry blind -1.2
extrude "Extruir142" add of existing geometry blind 1
delete_face "SuprimirCaras11"
sketch "Boceto43" plane through (0, 0, 14.5) normal (0, 0, -1) x axis (1, 0, 0)
  line L1 (-11, -57.5) -> (-11, -41)
  line L2 (11, -57.5) -> (-11, -57.5)
  line L3 (11, -41) -> (11, -57.5)
  line L4 (-11, -41) -> (11, -41)
  circle C1 centre (-0.0018, -49.25) radius 11
  circle C2 centre (-0.0018, -49.25) radius 8
  circle C3 centre (-9.5009, -49.25) radius 1.4991
  circle C4 centre (9.4991, -49.25) radius 1.5009
  concentric C1 C2
  tangent L1 C3
  tangent L3 C4
  dimension "d610" diameter C1 = 22
  dimension "d611" diameter C2 = 16
sketch "Boceto46" plane through (0, 0, 15.7363) normal (0, 0, -1) x axis (1, 0, 0)
  line L1 (-24.05, -66) -> (-24.05, 16.5)
  line L2 (24.05, -66) -> (-24.05, -66)
  line L3 (24.05, 16.5) -> (24.05, -66)
  line L4 (-24.05, 16.5) -> (24.05, 16.5)
  line L5 (10.9966, -41) -> (-11, -41)
  line L6 (10.9966, -57.5027) -> (10.9966, -41)
  line L7 (-11, -57.5027) -> (10.9966, -57.5027)
  line L8 (-11, -41) -> (-11, -57.5027)
  line L9 (-23.9661, -14.535) -> (24.05, -14.535)
  line L10 (-23.9661, -10.535) -> (-23.9661, -14.535)
  line L11 (24.05, -10.535) -> (-23.9661, -10.535)
  line L12 (24.05, -14.535) -> (24.05, -10.535)
  circle C1 centre (-17.9, -61.55) radius 1.6
  circle C2 centre (16.9814, -25.2578) radius 1.6
  circle C3 centre (-7.0114, -25.1758) radius 1.6
  circle C4 centre (16.994, 1.2507) radius 1.6
  circle C5 centre (-7.0048, 1.2479) radius 1.6
  circle C6 centre (-16.9759, 1.2458) radius 1.6
  circle C7 centre (7.0116, 1.2465) radius 1.6
  circle C8 centre (-16.9761, -25.1758) radius 1.6
  circle C9 centre (7.0062, -25.2517) radius 1.6
  circle C10 centre (17.9, -61.5514) radius 1.6
  point P20 (24.05, -14.535)
  point P23 (24.05, -10.535)
  horizontal L9
  vertical L10
  horizontal L11
  vertical L12
  coincident L3 P20
  dimension "d628" distance P20 P23 = 4
extrude "Extruir143" cut sketch "Boceto46" profile of L3 L9 L10 L11 L12 against normal blind 3
extrude "Extruir144" cut of existing geometry blind -10
sketch "Boceto47" plane through (-21.4222, 0, 0) normal (1, 0, 0) x axis (0, 1, 0)
  line L1 (14.535, 18.4363) -> (14.535, 18.7363)
  line L2 (63.8156, 18.4363) -> (14.535, 18.4363)
  line L3 (63.8156, 41.4363) -> (63.8156, 18.4363)
  line L4 (-13.7675, 41.4363) -> (63.8156, 41.4363)
  line L5 (-13.7675, 18.4363) -> (-13.7675, 41.4363)
  line L6 (10.535, 18.4363) -> (-13.7675, 18.4363)
  line L7 (10.535, 18.7363) -> (10.535, 18.4363)
  line L8 (14.535, 18.7363) -> (10.535, 18.7363)
  line L9 (14.535, 18.7363) -> (10.535, 18.7363)
  line L10 (14.535, 41.4363) -> (14.535, 18.7363)
  line L11 (10.535, 41.4363) -> (14.535, 41.4363)
  line L12 (10.535, 18.7363) -> (10.535, 41.4363)
  point P12 (14.535, 41.4363)
  point P9 (10.535, 18.7363)
  point P10 (10.535, 18.7363)
  horizontal L9
  vertical L10
  horizontal L11
  vertical L12
  coincident L4 P12
  coincident P9 P10
sketch "Boceto48" plane through (0, 0, 41.4363) normal (0, 0, 1) x axis (-1, 0, 0)
  line L1 (-22.3879, 15.5) -> (-22.3855, 15.5)
  line L2 (-25.6833, 15.4985) -> (-25.6858, 15.4985)
  line L3 (-27.0362, 15.5) -> (-27.0338, 15.5)
  line L4 (-24.05, -66) -> (-24.05, 12.4412)
  line L5 (21.064, -66) -> (-24.05, -66)
  line L6 (21.064, -65.0235) -> (21.064, -66)
  line L7 (24.05, 16.5) -> (24.05, -62.0118)
  line L8 (-21.035, 16.5) -> (24.05, 16.5)
  line L9 (-21.035, 15.5) -> (-21.035, 16.5)
  line L10 (-21.5363, 13.7675) -> (-21.5363, -63.8156)
  line L11 (21.4222, 13.7675) -> (-21.5363, 13.7675)
  line L12 (21.4222, -63.8156) -> (21.4222, 13.7675)
  line L13 (-21.5363, -63.8156) -> (21.4222, -63.8156)
  line L14 (24.05, -14.5268) -> (21.4222, -14.5268)
  line L15 (24.05, -10.5037) -> (24.05, -14.5268)
  line L16 (21.4222, -10.5037) -> (24.05, -10.5037)
  line L17 (21.4222, -14.5268) -> (21.4222, -10.5037)
  line L18 (-24.05, -14.5268) -> (-21.5363, -14.5268)
  line L19 (-24.05, -10.5037) -> (-24.05, -14.5268)
  line L20 (-21.5363, -10.5037) -> (-24.05, -10.5037)
  line L21 (-21.5363, -14.5268) -> (-21.5363, -10.5037)
  line L22 (9.937, 13.7675) -> (14.9626, 13.7675)
  line L23 (9.937, 16.5) -> (9.937, 13.7675)
  line L24 (14.9626, 16.5) -> (9.937, 16.5)
  line L25 (14.9626, 13.7675) -> (14.9626, 16.5)
  line L26 (9.937, 15.1337) -> (14.9626, 15.1337)
  line L27 (9.937, 13.7675) -> (9.937, 15.1337)
  line L28 (14.9626, 13.7675) -> (9.937, 13.7675)
  line L29 (14.9626, 15.1337) -> (14.9626, 13.7675)
  arc A1 centre (-24.0344, 15.4397) radius 1.65 clockwise from (-25.6833, 15.4985) to (-22.3855, 15.5)
  arc A2 centre (-24.0368, 15.4412) radius 1.65 clockwise from (-22.3879, 15.5) to (-25.6858, 15.4985)
  arc A3 centre (-24.0344, 15.4397) radius 3 clockwise from (-27.0338, 15.5) to (-21.035, 15.5)
  arc A4 centre (-24.0368, 15.4412) radius 3 clockwise from (-24.05, 12.4412) to (-27.0362, 15.5)
  arc A5 centre (24.064, -65.0117) radius 3 clockwise from (24.05, -62.0118) to (21.064, -65.0235)
  circle C1 centre (24.064, -65.0117) radius 1.65
  point P25 (24.05, -10.5037)
  point P23 (21.4222, -14.5268)
  point P29 (-24.05, -10.5037)
  point P27 (-21.5363, -14.5268)
  point P33 (9.937, 16.5)
  point P31 (14.9626, 13.7675)
  horizontal L14
  vertical L15
  horizontal L16
  vertical L17
  coincident L7 P25
  coincident L12 P23
  horizontal L18
  vertical L19
  horizontal L20
  vertical L21
  coincident L4 P29
  coincident L10 P27
  horizontal L22
  vertical L23
  horizontal L24
  vertical L25
  coincident L8 P33
  coincident L11 P31
  horizontal L26
  vertical L27
  horizontal L28
  vertical L29
extrude "Extruir145" cut sketch "Boceto47" profile of L4 L8 L9 L10 L11 L12 along normal blind 44.5
extrude "Extruir146" cut sketch "Boceto47" profile of L4 L8 L9 L10 L11 L12 against normal blind 1.5
extrude "Extruir147" add of existing geometry blind 0.3
extrude "Extruir148" cut sketch "Boceto48" profile of L11 L22 L23 L25 L26 L27 L28 L29 against normal blind 23
sketch "Boceto49" plane through (0, 14.535, 0) normal (0, -1, 0) x axis (1, 0, 0)
  line L1 (22.7778, 18.7363) -> (24.05, 18.7363)
  line L2 (22.7778, 41.4363) -> (22.7778, 18.7363)
  line L3 (21.5363, 41.4363) -> (22.7778, 41.4363)
  line L4 (21.5363, 18.4363) -> (21.5363, 41.4363)
  line L5 (-21.4222, 18.4363) -> (21.5363, 18.4363)
  line L6 (-21.4222, 41.4363) -> (-21.4222, 18.4363)
  line L7 (-22.9222, 41.4363) -> (-21.4222, 41.4363)
  line L8 (-22.9222, 18.7363) -> (-22.9222, 41.4363)
  line L9 (-24.05, 18.7363) -> (-22.9222, 18.7363)
  line L10 (-24.05, 15.7363) -> (-24.05, 18.7363)
  line L11 (24.05, 15.7363) -> (-24.05, 15.7363)
  line L12 (24.05, 18.7363) -> (24.05, 15.7363)
  line L13 (24.05, 15.7363) -> (-24.05, 15.7363)
  line L14 (24.05, 17.2363) -> (24.05, 15.7363)
  line L15 (-24.05, 17.2363) -> (24.05, 17.2363)
  line L16 (-24.05, 15.7363) -> (-24.05, 17.2363)
  line L17 (6.944, 17.2363) -> (-7.056, 17.2363)
  line L18 (6.944, 15.7363) -> (6.944, 17.2363)
  line L19 (-7.056, 15.7363) -> (6.944, 15.7363)
  line L20 (-7.056, 17.2363) -> (-7.056, 15.7363)
  point P16 (24.05, 17.2363)
  point P12 (-24.05, 15.7363)
  point P14 (-24.05, 15.7363)
  point P18 (-7.056, 17.2363)
  point P19 (6.944, 17.2363)
  horizontal L13
  vertical L14
  horizontal L15
  vertical L16
  midpoint L12 P16
  coincident P12 P14
  horizontal L17
  vertical L18
  horizontal L19
  vertical L20
  coincident L15 P18
  dimension "d641" distance P18 P19 = 14
extrude "Extruir149" add sketch "Boceto49" profile of L10 L11 L12 L13 L14 L15 L16 L18 L20 along normal blind 5
extrude "Extruir150" cut sketch "Boceto48" profile of L4 L7 L8 L10 L12 L14 L15 L16 L17 L18 L19 L20 L21 L23 L24 L25 L26 against normal blind 2
sketch "Boceto50" plane through (0, 0, 9.3) normal (0, 0, 1) x axis (-1, 0, 0)
  line L1 (-15, -62.5) -> (15, -62.5)
  line L2 (-15, -56.5) -> (-15, -62.5)
  line L3 (-26, -56.5) -> (-15, -56.5)
  line L4 (-26, -50.25) -> (-26, -56.5)
  line L5 (-33.25, -75.86) -> (-33.25, -57.5)
  line L6 (33.25, -75.86) -> (-33.25, -75.86)
  line L7 (33.25, -57.5) -> (33.25, -75.86)
  line L8 (26, -56.5) -> (26, -50.25)
  line L9 (15, -56.5) -> (26, -56.5)
  line L10 (15, -62.5) -> (15, -56.5)
  line L11 (-21.2755, -56.5) -> (-26, -56.5)
  line L12 (-21.2755, -63.524) -> (-21.2755, -56.5)
  line L13 (-26, -63.524) -> (-21.2755, -63.524)
  line L14 (-26, -56.5) -> (-26, -63.524)
  line L15 (21.444, -56.5) -> (26, -56.5)
  line L16 (21.444, -63.524) -> (21.444, -56.5)
  line L17 (26, -63.524) -> (21.444, -63.524)
  line L18 (26, -56.5) -> (26, -63.524)
  arc A1 centre (-26, -57.5) radius 7.25 clockwise from (-33.25, -57.5) to (-26, -50.25)
  arc A2 centre (26, -57.5) radius 7.25 clockwise from (26, -50.25) to (33.25, -57.5)
  arc A3 centre (-17.9, -61.5514) radius 1.85 clockwise from (-19.3644, -60.4208) to (-19.683, -61.0577)
  arc A4 centre (-26, -57.5) radius 7.25 clockwise from (-19.3644, -60.4208) to (-19.683, -61.0577)
  arc A5 centre (17.9, -61.55) radius 1.85 clockwise from (19.6836, -61.0589) to (19.363, -60.4177)
  arc A6 centre (26, -57.5) radius 7.25 clockwise from (19.6836, -61.0589) to (19.363, -60.4177)
  point P5 (-26, -56.5)
  point P22 (-26, -56.5)
  point P14 (26, -56.5)
  point P26 (26, -56.5)
  horizontal L11
  vertical L12
  horizontal L13
  vertical L14
  coincident P5 P22
  horizontal L15
  vertical L16
  horizontal L17
  vertical L18
  coincident P14 P26
extrude "Extruir151" add sketch "Boceto50" profile of L3 L9 L11 L12 L13 L14 L15 L16 L17 L18 along normal blind 5
fillet "Empalme1" radius 1
fillet "Empalme2" radius 0.5
fillet "Empalme3" radius 0.5
extrude "Extruir152" add of existing geometry blind 1
extrude "Extruir153" add of existing geometry blind 1
hole "Agujero74" HoleDepth 40 HoleDiameter 1.9 TipAngle 180 RefDim1 2 RefDim2 8.25
hole "Agujero75" HoleDepth 40 HoleDiameter 1.9 TipAngle 180 RefDim1 2 RefDim2 8.25
fillet "Empalme4" radius 1
fillet "Empalme5" radius 0.5
move "Desplazar115"
extrude "Extruir154" cut of existing geometry blind -2
extrude "Extruir155" cut of existing geometry blind -0.2
extrude "Extruir156" cut of existing geometry blind -0.05
extrude "Extruir157" cut of existing geometry blind -0.2
sketch "Boceto51" plane through (-33.5, 0, 0) normal (1, 0, 0) x axis (0, 1, 0)
  line L1 (130, 3.35) -> (113, 3.35)
  line L2 (130, 5.9) -> (130, 3.35)
  line L3 (113, 5.9) -> (130, 5.9)
  line L4 (113, 3.35) -> (113, 5.9)
  line L5 (113, 4) -> (130, 5.9)
  point P4 (130, 5.9)
  point P6 (130, 5.9)
  point P7 (113, 4)
  coincident P4 P6
  coincident L4 P7
extrude "Extruir160" cut of existing geometry blind -0.2
sketch "Boceto52" plane through (-33.5, 0, 0) normal (1, 0, 0) x axis (0, 1, 0)
  line L1 (113, 6) -> (113, 4)
  line L2 (130, 6) -> (113, 6)
  line L3 (130, 5.9) -> (130, 6)
  line L4 (113, 4) -> (130, 5.9)
  vertical L1
  perpendicular L1 L2
  perpendicular L2 L3
extrude "Extruir161" add sketch "Boceto52" along normal blind 12
extrude "Extruir162" add of existing geometry blind 55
